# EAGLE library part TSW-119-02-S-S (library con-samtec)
THROUGH-HOLE .025" SQ POST HEADER Source: Samtec TSW.pdf
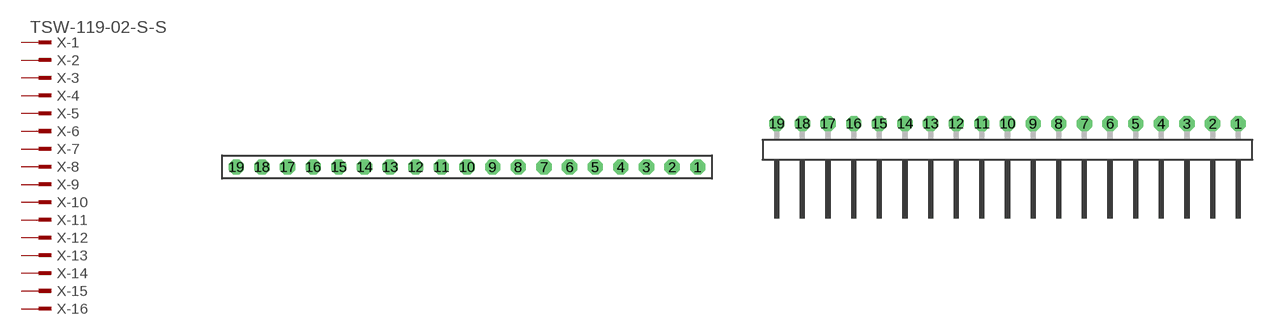
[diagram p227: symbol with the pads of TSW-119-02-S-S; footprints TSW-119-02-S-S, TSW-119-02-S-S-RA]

Designator prefix X; gates -1=MPINV -2=MPIN -3=MPIN -4=MPIN -5=MPIN -6=MPIN -7=MPIN -8=MPIN -9=MPIN -10=MPIN -11=MPIN -12=MPIN -13=MPIN -14=MPIN -15=MPIN -16=MPIN -17=MPIN -18=MPIN -19=MPIN

## TSW-119-02-S-S (OC_FARNELL: unknown; OC_NEWARK: unknown)  [TSW-119-02-S-S]
1  -1:1  pas
2  -2:1  pas
3  -3:1  pas
4  -4:1  pas
5  -5:1  pas
6  -6:1  pas
7  -7:1  pas
8  -8:1  pas
9  -9:1  pas
10  -10:1  pas
11  -11:1  pas
12  -12:1  pas
13  -13:1  pas
14  -14:1  pas
15  -15:1  pas
16  -16:1  pas
17  -17:1  pas
18  -18:1  pas
19  -19:1  pas

## TSW-119-02-S-S-RA (OC_FARNELL: unknown; OC_NEWARK: unknown)  [TSW-119-02-S-S-RA]
Pads as for TSW-119-02-S-S

## Footprint TSW-119-02-S-S (pad centres in mm)
THROUGH-HOLE .025" SQ POST HEADER Source: Samtec TSW.pdf
drill 1 pad 1.5 octagon: 1 22.86,0; 2 20.32,0; 3 17.78,0; 4 15.24,0; 5 12.7,0; 6 10.16,0; 7 7.62,0; 8 5.08,0; 9 2.54,0; 10 0,0; 11 -2.54,0; 12 -5.08,0; 13 -7.62,0; 14 -10.16,0; 15 -12.7,0; 16 -15.24,0; 17 -17.78,0; 18 -20.32,0; 19 -22.86,0

## Footprint TSW-119-02-S-S-RA (pad centres in mm)
THROUGH-HOLE .025" SQ POST HEADER Source: Samtec TSW.pdf
drill 1 pad 1.5 octagon: 1 22.86,1.524; 2 20.32,1.524; 3 17.78,1.524; 4 15.24,1.524; 5 12.7,1.524; 6 10.16,1.524; 7 7.62,1.524; 8 5.08,1.524; 9 2.54,1.524; 10 0,1.524; 11 -2.54,1.524; 12 -5.08,1.524; 13 -7.62,1.524; 14 -10.16,1.524; 15 -12.7,1.524; 16 -15.24,1.524; 17 -17.78,1.524; 18 -20.32,1.524; 19 -22.86,1.524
